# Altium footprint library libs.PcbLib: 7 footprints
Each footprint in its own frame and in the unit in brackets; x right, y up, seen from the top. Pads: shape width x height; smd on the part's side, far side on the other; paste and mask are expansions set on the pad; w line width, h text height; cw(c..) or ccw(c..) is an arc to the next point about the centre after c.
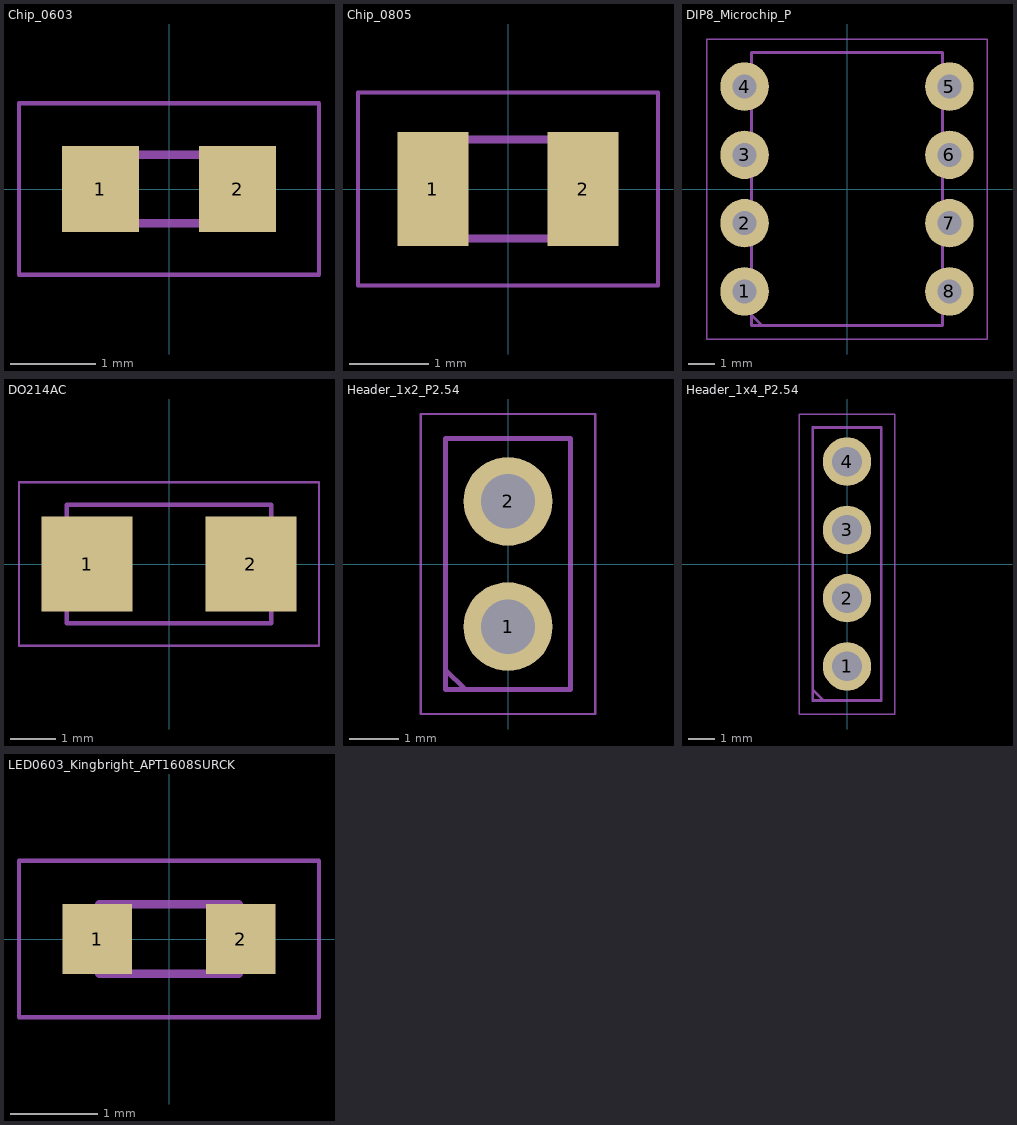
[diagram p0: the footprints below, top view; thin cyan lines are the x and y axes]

## Chip_0603 [mm] "Generic two-terminal 0603 chip land; land pattern remains INFERRED and requires part-specific review"
pads (2):
  rect 0.9x1 smd: 1(-0.8,0) 2(0.8,0)
Mechanical 13:
  lines w0.1: -0.8,-0.4 0.8,-0.4 0.8,0.4 -0.8,0.4 -0.8,-0.4
Mechanical 15:
  lines w0.05: -1.75,-1 1.75,-1 1.75,1 -1.75,1 -1.75,-1

## Chip_0805 [mm] "Generic two-terminal 0805 chip land; land pattern remains INFERRED and requires part-specific review"
pads (2):
  rect 0.9x1.45 smd: 1(-0.95,0) 2(0.95,0)
Mechanical 13:
  lines w0.1: -1,-0.625 1,-0.625 1,0.625 -1,0.625 -1,-0.625
Mechanical 15:
  lines w0.05: -1.9,-1.225 1.9,-1.225 1.9,1.225 -1.9,1.225 -1.9,-1.225

## DIP8_Microchip_P [mm] "8-lead manufacturer body with inferred 7.62 mm through-hole land; land pattern remains INFERRED and requires part-specific review"
pads (8):
  round 1.8 hole 0.9: 1(-3.81,-3.81) 2(-3.81,-1.27) 3(-3.81,1.27) 4(-3.81,3.81) 5(3.81,3.81) 6(3.81,1.27) 7(3.81,-1.27) 8(3.81,-3.81)
Mechanical 13:
  lines w0.1: -3.556,-4.68 -3.156,-5.08 ; -3.556,-5.08 3.556,-5.08 3.556,5.08 -3.556,5.08 -3.556,-5.08
Mechanical 15:
  lines w0.05: -5.21,-5.58 5.21,-5.58 5.21,5.58 -5.21,5.58 -5.21,-5.58

## DO214AC [mm] "Two-terminal DO-214AC / SMA land from manufacturer suggested layout; land pattern remains INFERRED and requires part-specific review"
pads (2):
  rect 2x2.1 smd: 1(-1.8,0) 2(1.8,0)
Mechanical 13:
  lines w0.1: -2.25,-1.3 2.25,-1.3 2.25,1.3 -2.25,1.3 -2.25,-1.3
Mechanical 15:
  lines w0.05: -3.3,-1.8 3.3,-1.8 3.3,1.8 -3.3,1.8 -3.3,-1.8

## Header_1x2_P2.54 [mm] "2-position generic 2.54 mm single-row header; land pattern remains INFERRED and requires part-specific review"
pads (2):
  round 1.8 hole 1.1: 1(0,-1.27) 2(0,1.27)
Mechanical 13:
  lines w0.1: -1.27,-2.14 -0.87,-2.54 ; -1.27,-2.54 1.27,-2.54 1.27,2.54 -1.27,2.54 -1.27,-2.54
Mechanical 15:
  lines w0.05: -1.77,-3.04 1.77,-3.04 1.77,3.04 -1.77,3.04 -1.77,-3.04

## Header_1x4_P2.54 [mm] "4-position generic 2.54 mm single-row header; land pattern remains INFERRED and requires part-specific review"
pads (4):
  round 1.8 hole 1.1: 1(0,-3.81) 2(0,-1.27) 3(0,1.27) 4(0,3.81)
Mechanical 13:
  lines w0.1: -1.27,-4.68 -0.87,-5.08 ; -1.27,-5.08 1.27,-5.08 1.27,5.08 -1.27,5.08 -1.27,-5.08
Mechanical 15:
  lines w0.05: -1.77,-5.58 1.77,-5.58 1.77,5.58 -1.77,5.58 -1.77,-5.58

## LED0603_Kingbright_APT1608SURCK [mm] "Kingbright APT1608SURCK LED suggested land, pin 1 cathode; land pattern remains INFERRED and requires part-specific review"
pads (2):
  rect 0.8x0.8 smd: 1(-0.825,0) 2(0.825,0)
Mechanical 13:
  lines w0.1: -0.6,-0.25 -0.6,0.25 ; -0.8,-0.4 0.8,-0.4 0.8,0.4 -0.8,0.4 -0.8,-0.4
Mechanical 15:
  lines w0.05: -1.725,-0.9 1.725,-0.9 1.725,0.9 -1.725,0.9 -1.725,-0.9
